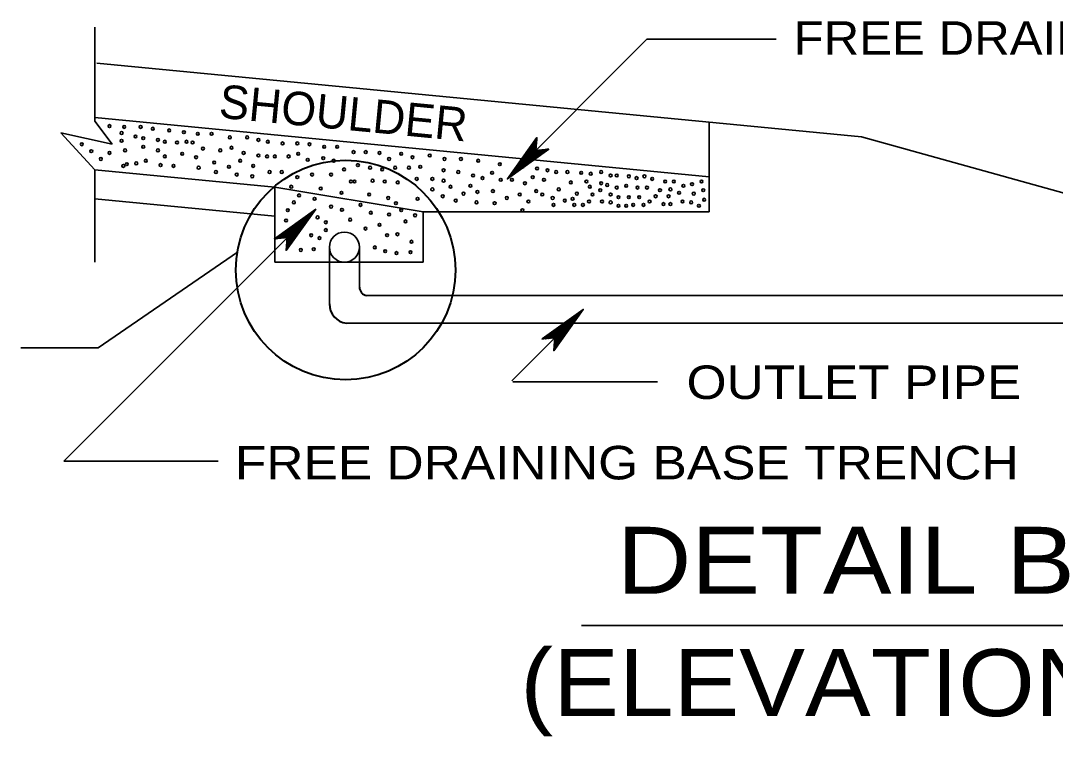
# Model space of a CAD drawing. Extents: x -48732 to -48696.6, y -117659.8 to -117637.8.
# Drawn here: x -48725.962 to -48722.254, y -117651.452 to -117648.889 of the extents above; entities that cross this region are included whole.
import ezdxf

# ---------------------------------------------------------------- set-up
doc = ezdxf.new("R2010")
doc.units = 0
doc.header["$LTSCALE"] = 0.048
doc.layers.add('1', color=7, linetype='Continuous', lineweight=25)
doc.layers.add('3', color=7, linetype='Continuous', lineweight=35)

msp = doc.modelspace()

# ---------------------------------------------------------------- linework, layer by layer
at = {"layer": '1', "lineweight": 40}
msp.add_circle((-48724.79747, -117649.78235), 0.39328, dxfattribs=at)
for centre, radius, end in [((-48724.71775, -117649.84392), 0.03, 262.57441), ((-48724.78575, -117649.90358), 0.07, 262.57442)]:
    msp.add_arc(centre, radius, 180, end, dxfattribs=at)
at = {"layer": '3'}
for p, q in [((-48725.69675, -117648.91233), (-48725.69675, -117649.24933)), ((-48725.68975, -117649.04133), (-48722.94875, -117649.30533)), ((-48725.69675, -117649.23633), (-48723.49475, -117649.44833)), ((-48725.69675, -117649.24933), (-48725.63475, -117649.33133)), ((-48723.49475, -117649.25233), (-48723.49475, -117649.57433)), ((-48725.81775, -117649.29133), (-48725.69675, -117649.42333)), ((-48725.81775, -117649.29133), (-48725.63475, -117649.33133)), ((-48725.69675, -117649.42333), (-48725.69675, -117649.75433)), ((-48725.05075, -117649.48533), (-48724.51975, -117649.57433)), ((-48725.69675, -117649.52733), (-48725.05075, -117649.58933)), ((-48725.807, -117650.46658), (-48724.90475, -117649.56433)), ((-48724.51975, -117649.57433), (-48723.49475, -117649.57433)), ((-48724.51975, -117649.75433), (-48724.51975, -117649.57433)), ((-48724.85575, -117649.70033), (-48724.85575, -117649.90358)), ((-48724.74775, -117649.70033), (-48724.74775, -117649.84392)), ((-48725.05075, -117649.75433), (-48724.51975, -117649.75433)), ((-48724.72167, -117649.87367), (-48721.0215, -117649.87367)), ((-48724.2015, -117650.17908), (-48723.94558, -117649.92317)), ((-48724.79483, -117649.973), (-48719.98, -117649.973)), ((-48724.19817, -117650.18242), (-48723.67958, -117650.18242)), ((-48725.807, -117650.46658), (-48725.25475, -117650.46658)), ((-48723.95158, -117651.05517), (-48722.19658, -117651.05517))]:
    msp.add_line(p, q, dxfattribs=at)
for points in [[(-48724.21767, -117649.45567), (-48723.71767, -117648.95567), (-48723.25467, -117648.95567)], [(-48724.11167, -117649.30767), (-48724.21767, -117649.45567), (-48724.06967, -117649.34967), (-48724.07467, -117649.34967), (-48724.20467, -117649.44267), (-48724.11167, -117649.31267), (-48724.11267, -117649.31867), (-48724.19167, -117649.42967), (-48724.08067, -117649.35067), (-48724.08667, -117649.35167), (-48724.17867, -117649.41667), (-48724.11367, -117649.32467), (-48724.11367, -117649.33067), (-48724.16567, -117649.40367), (-48724.09267, -117649.35167), (-48724.09867, -117649.35267), (-48724.15367, -117649.39167), (-48724.11467, -117649.33667), (-48724.11467, -117649.34267), (-48724.14067, -117649.37867), (-48724.10467, -117649.35267), (-48724.11067, -117649.35367), (-48724.12767, -117649.36567), (-48724.11567, -117649.34867), (-48724.11167, -117649.30767), (-48724.11567, -117649.35367), (-48724.06967, -117649.34967)], [(-48720.54708, -117649.973), (-48721.58208, -117649.68525), (-48722.94875, -117649.30533)], [(-48725.69675, -117649.42333), (-48725.05075, -117649.48533), (-48725.05075, -117649.75433)], [(-48725.01075, -117649.71233), (-48724.90475, -117649.56433), (-48725.05275, -117649.67033), (-48725.04775, -117649.67033), (-48724.91775, -117649.57733), (-48725.01075, -117649.70733), (-48725.00975, -117649.70133), (-48724.93075, -117649.59033), (-48725.04175, -117649.66933), (-48725.03575, -117649.66833), (-48724.94375, -117649.60333), (-48725.00875, -117649.69533), (-48725.00875, -117649.68933), (-48724.95675, -117649.61633), (-48725.02975, -117649.66833), (-48725.02375, -117649.66733), (-48724.96875, -117649.62833), (-48725.00775, -117649.68333), (-48725.00775, -117649.67733), (-48724.98175, -117649.64133), (-48725.01775, -117649.66733), (-48725.01175, -117649.66633), (-48724.99475, -117649.65433), (-48725.00675, -117649.67133), (-48725.01075, -117649.71233), (-48725.00675, -117649.66633), (-48725.05275, -117649.67033)], [(-48725.96208, -117650.06083), (-48725.68467, -117650.06083), (-48725.18558, -117649.71875)], [(-48724.05158, -117650.07117), (-48723.94558, -117649.92317), (-48724.09358, -117650.02917), (-48724.08858, -117650.02917), (-48723.95858, -117649.93617), (-48724.05158, -117650.06617), (-48724.05058, -117650.06017), (-48723.97158, -117649.94917), (-48724.08258, -117650.02817), (-48724.07658, -117650.02717), (-48723.98458, -117649.96217), (-48724.04958, -117650.05417), (-48724.04958, -117650.04817), (-48723.99758, -117649.97517), (-48724.07058, -117650.02717), (-48724.06458, -117650.02617), (-48724.00958, -117649.98717), (-48724.04858, -117650.04217), (-48724.04858, -117650.03617), (-48724.02258, -117650.00017), (-48724.05858, -117650.02617), (-48724.05258, -117650.02517), (-48724.03558, -117650.01317), (-48724.04758, -117650.03017), (-48724.05158, -117650.07117), (-48724.04758, -117650.02517), (-48724.09358, -117650.02917)]]:
    msp.add_lwpolyline(points, dxfattribs=at)
for centre, radius in [((-48725.64383, -117649.26667), 0.00515), ((-48725.60033, -117649.2915), 0.00515), ((-48725.59108, -117649.26975), 0.00515), ((-48725.53208, -117649.26975), 0.00515), ((-48725.48867, -117649.276), 0.00515), ((-48725.42975, -117649.28217), 0.00515), ((-48725.377, -117649.28842), 0.00515), ((-48725.32733, -117649.29458), 0.00515), ((-48725.27775, -117649.29458), 0.00515), ((-48725.74308, -117649.33183), 0.00515), ((-48725.60033, -117649.31942), 0.00515), ((-48725.55075, -117649.30392), 0.00515), ((-48725.52283, -117649.31017), 0.00515), ((-48725.47008, -117649.31633), 0.00515), ((-48725.44525, -117649.32258), 0.00515), ((-48725.40183, -117649.32567), 0.00515), ((-48725.36767, -117649.32258), 0.00515), ((-48725.346, -117649.32567), 0.00515), ((-48725.21258, -117649.307), 0.00515), ((-48725.15058, -117649.307), 0.00515), ((-48725.11025, -117649.31633), 0.00515), ((-48725.07608, -117649.32258), 0.00515), ((-48725.02333, -117649.32875), 0.00515), ((-48724.97058, -117649.32875), 0.00515), ((-48724.92717, -117649.33183), 0.00515), ((-48725.70892, -117649.35667), 0.00515), ((-48725.64383, -117649.36292), 0.00515), ((-48725.588, -117649.35358), 0.00515), ((-48725.52283, -117649.34117), 0.00515), ((-48725.47008, -117649.35358), 0.00515), ((-48725.38325, -117649.366), 0.00515), ((-48725.30875, -117649.34742), 0.00515), ((-48725.24675, -117649.35358), 0.00515), ((-48725.20642, -117649.34425), 0.00515), ((-48725.16292, -117649.36292), 0.00515), ((-48725.11025, -117649.37217), 0.00515), ((-48724.9675, -117649.366), 0.00515), ((-48724.87442, -117649.34117), 0.00515), ((-48724.82792, -117649.34117), 0.00515), ((-48724.769, -117649.35983), 0.00515), ((-48724.7255, -117649.35983), 0.00515), ((-48724.67592, -117649.36292), 0.00515), ((-48724.59833, -117649.366), 0.00515), ((-48724.496, -117649.37217), 0.00515), ((-48725.67483, -117649.38458), 0.00515), ((-48725.58175, -117649.40325), 0.00515), ((-48725.54767, -117649.40017), 0.00515), ((-48725.5135, -117649.39083), 0.00515), ((-48725.46075, -117649.40633), 0.00515), ((-48725.44525, -117649.37533), 0.00515), ((-48725.33358, -117649.37842), 0.00515), ((-48725.26842, -117649.397), 0.00515), ((-48725.17533, -117649.39083), 0.00515), ((-48725.07917, -117649.37533), 0.00515), ((-48725.05125, -117649.37533), 0.00515), ((-48725.00167, -117649.37533), 0.00515), ((-48724.93342, -117649.38775), 0.00515), ((-48724.87758, -117649.3815), 0.00515), ((-48724.84033, -117649.39083), 0.00515), ((-48724.75342, -117649.40633), 0.00515), ((-48724.64175, -117649.38458), 0.00515), ((-48724.558, -117649.37842), 0.00515), ((-48724.44325, -117649.38458), 0.00515), ((-48724.38425, -117649.38458), 0.00515), ((-48724.32225, -117649.39083), 0.00515), ((-48724.24467, -117649.40325), 0.00515), ((-48725.59417, -117649.40942), 0.00515), ((-48725.41425, -117649.40942), 0.00515), ((-48725.32425, -117649.41567), 0.00515), ((-48725.26225, -117649.43117), 0.00515), ((-48725.21567, -117649.41258), 0.00515), ((-48725.18775, -117649.4405), 0.00515), ((-48725.12883, -117649.40942), 0.00515), ((-48725.06992, -117649.43117), 0.00515), ((-48725.02642, -117649.43117), 0.00515), ((-48724.91792, -117649.4405), 0.00515), ((-48724.84967, -117649.4405), 0.00515), ((-48724.80308, -117649.42183), 0.00515), ((-48724.71, -117649.41567), 0.00515), ((-48724.66658, -117649.42183), 0.00515), ((-48724.62008, -117649.41567), 0.00515), ((-48724.57042, -117649.41567), 0.00515), ((-48724.53008, -117649.41258), 0.00515), ((-48724.44633, -117649.425), 0.00515), ((-48724.39358, -117649.43117), 0.00515), ((-48724.34083, -117649.44358), 0.00515), ((-48724.27258, -117649.43425), 0.00515), ((-48724.164, -117649.41258), 0.00515), ((-48724.11133, -117649.41875), 0.00515), ((-48724.07408, -117649.425), 0.00515), ((-48724.04308, -117649.43117), 0.00515), ((-48724.00275, -117649.43117), 0.00515), ((-48723.95308, -117649.43425), 0.00515), ((-48723.91892, -117649.43742), 0.00515), ((-48723.88175, -117649.43117), 0.00515), ((-48723.84758, -117649.44358), 0.00515), ((-48723.82592, -117649.44358), 0.00515), ((-48725.13192, -117649.44667), 0.00515), ((-48724.97058, -117649.44983), 0.00515), ((-48724.77825, -117649.46533), 0.00515), ((-48724.76583, -117649.46533), 0.00515), ((-48724.70075, -117649.46225), 0.00515), ((-48724.65725, -117649.46533), 0.00515), ((-48724.61075, -117649.46842), 0.00515), ((-48724.5425, -117649.456), 0.00515), ((-48724.48667, -117649.456), 0.00515), ((-48724.44633, -117649.46225), 0.00515), ((-48724.35017, -117649.48083), 0.00515), ((-48724.30675, -117649.45292), 0.00515), ((-48724.24158, -117649.45908), 0.00515), ((-48724.20125, -117649.45908), 0.00515), ((-48724.15475, -117649.4715), 0.00515), ((-48724.12683, -117649.44983), 0.00515), ((-48724.0865, -117649.45908), 0.00515), ((-48723.99033, -117649.46842), 0.00515), ((-48723.9345, -117649.46533), 0.00515), ((-48723.88175, -117649.4715), 0.00515), ((-48723.86, -117649.47775), 0.00515), ((-48723.79175, -117649.48083), 0.00515), ((-48723.78242, -117649.44667), 0.00515), ((-48723.7545, -117649.45292), 0.00515), ((-48723.72658, -117649.44667), 0.00515), ((-48723.69867, -117649.456), 0.00515), ((-48723.65217, -117649.46533), 0.00515), ((-48723.62117, -117649.46533), 0.00515), ((-48723.587, -117649.48083), 0.00515), ((-48723.556, -117649.47467), 0.00515), ((-48723.52183, -117649.46533), 0.00515), ((-48724.99233, -117649.48392), 0.00515), ((-48724.96442, -117649.515), 0.00515), ((-48724.88683, -117649.49017), 0.00515), ((-48724.81242, -117649.50567), 0.00515), ((-48724.71317, -117649.51183), 0.00515), ((-48724.48667, -117649.49325), 0.00515), ((-48724.44942, -117649.51808), 0.00515), ((-48724.4215, -117649.48392), 0.00515), ((-48724.375, -117649.50875), 0.00515), ((-48724.32533, -117649.50258), 0.00515), ((-48724.2695, -117649.49942), 0.00515), ((-48724.17333, -117649.51183), 0.00515), ((-48724.11442, -117649.49942), 0.00515), ((-48724.09267, -117649.51183), 0.00515), ((-48724.03375, -117649.49325), 0.00515), ((-48723.96858, -117649.50875), 0.00515), ((-48723.92208, -117649.48392), 0.00515), ((-48723.91275, -117649.51183), 0.00515), ((-48723.88483, -117649.49633), 0.00515), ((-48723.84758, -117649.51183), 0.00515), ((-48723.82592, -117649.48708), 0.00515), ((-48723.75142, -117649.48708), 0.00515), ((-48723.71733, -117649.48708), 0.00515), ((-48723.68625, -117649.51808), 0.00515), ((-48723.67075, -117649.49633), 0.00515), ((-48723.63975, -117649.51808), 0.00515), ((-48723.63358, -117649.49325), 0.00515), ((-48723.6025, -117649.50567), 0.00515), ((-48723.54975, -117649.50875), 0.00515), ((-48723.51567, -117649.49633), 0.00515), ((-48724.983, -117649.53983), 0.00515), ((-48724.90858, -117649.52742), 0.00515), ((-48724.84967, -117649.55533), 0.00515), ((-48724.74417, -117649.54908), 0.00515), ((-48724.64492, -117649.52425), 0.00515), ((-48724.617, -117649.54292), 0.00515), ((-48724.53942, -117649.52742), 0.00515), ((-48724.40292, -117649.53358), 0.00515), ((-48724.32842, -117649.53983), 0.00515), ((-48724.26333, -117649.54292), 0.00515), ((-48724.21983, -117649.52425), 0.00515), ((-48724.14233, -117649.53667), 0.00515), ((-48724.05542, -117649.52425), 0.00515), ((-48724.05233, -117649.54908), 0.00515), ((-48724.012, -117649.53358), 0.00515), ((-48723.98408, -117649.52742), 0.00515), ((-48723.97792, -117649.54908), 0.00515), ((-48723.94683, -117649.54908), 0.00515), ((-48723.92517, -117649.53667), 0.00515), ((-48723.87858, -117649.53667), 0.00515), ((-48723.84758, -117649.53983), 0.00515), ((-48723.81967, -117649.52117), 0.00515), ((-48723.81967, -117649.55225), 0.00515), ((-48723.79175, -117649.55225), 0.00515), ((-48723.78242, -117649.52117), 0.00515), ((-48723.76692, -117649.54908), 0.00515), ((-48723.74525, -117649.52117), 0.00515), ((-48723.72975, -117649.54908), 0.00515), ((-48723.708, -117649.53667), 0.00515), ((-48723.65833, -117649.546), 0.00515), ((-48723.63358, -117649.546), 0.00515), ((-48723.59008, -117649.53667), 0.00515), ((-48723.55908, -117649.53983), 0.00515), ((-48723.53117, -117649.55225), 0.00515), ((-48723.51258, -117649.5305), 0.00515), ((-48725.00475, -117649.56775), 0.00515), ((-48724.89792, -117649.59356), 0.00515), ((-48724.8105, -117649.56664), 0.00515), ((-48724.70692, -117649.57708), 0.00515), ((-48724.64175, -117649.58325), 0.00515), ((-48724.59833, -117649.56775), 0.00515), ((-48724.54875, -117649.58633), 0.00515), ((-48724.164, -117649.56775), 0.00515), ((-48725.01092, -117649.605), 0.00515), ((-48724.86825, -117649.61117), 0.00515), ((-48724.78142, -117649.60192), 0.00515), ((-48724.67592, -117649.6205), 0.00515), ((-48724.58283, -117649.60808), 0.00515), ((-48724.921, -117649.65775), 0.00515), ((-48724.89117, -117649.66764), 0.00515), ((-48724.86825, -117649.63908), 0.00515), ((-48724.80175, -117649.70033), 0.054), ((-48724.72633, -117649.63397), 0.00515), ((-48724.649, -117649.65756), 0.00515), ((-48724.612, -117649.65414), 0.00515), ((-48724.69275, -117649.70131), 0.00515), ((-48724.56158, -117649.68106), 0.00515), ((-48724.95817, -117649.7105), 0.00515), ((-48724.91167, -117649.70742), 0.00515), ((-48724.65575, -117649.71472), 0.00515), ((-48724.61533, -117649.72147), 0.00515), ((-48724.56492, -117649.71814), 0.00515)]:
    msp.add_circle(centre, radius, dxfattribs=at)

# ---------------------------------------------------------------- texts
for s, height, width, p in [('FREE DRAINING BASE', 0.12, 1.1, (-48723.19208, -117649.011)), ('OUTLET PIPE', 0.12, 1.15, (-48723.5755, -117650.24425)), ('FREE DRAINING BASE TRENCH', 0.12, 1.15, (-48725.1945, -117650.53225)), ('DETAIL B', 0.24, 1.15, (-48723.825, -117650.942)), ('(ELEVATION)', 0.24, 1.1, (-48724.17125, -117651.38025))]:
    msp.add_text(s, height=height, dxfattribs=dict(at, width=width)).set_placement(p)
msp.add_text('SHOULDER', height=0.12, rotation=354.497, dxfattribs=at).set_placement((-48725.25475, -117649.23633))

doc.saveas('drawing.dxf')
